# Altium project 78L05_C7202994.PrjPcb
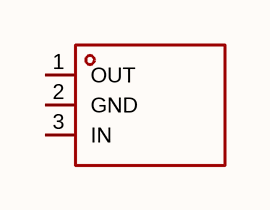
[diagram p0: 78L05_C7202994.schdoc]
1 sheet, 1 parts. Net scope: global (net labels, ports and power ports of the same name join across sheets).

## Sheet 78L05_C7202994.schdoc
size 127 x 101 mm

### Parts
U?  78l05_c7202994  [SOT-89-3_L4.5-W2.5-P1.50-LS4.2-BR]  (value not drawn)

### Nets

Not connected (* = marked no-connect by the designer): U? 1(OUT) 2(GND) 3(IN)

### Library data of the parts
U? = 78l05_c7202994: 输出极性:正极;工作电压:30V;输出电压:5V;输出电流:100mA;电源纹波抑制比(PSRR):49dB@(120Hz);输出类型:固定;; Manufacturer: TECH PUBLIC(台舟); ManufacturerPart: 78L05; AddInBom: yes; ModelId: 6db690b7897d4d18a30d90c1b89525ee; ModelName: SOT-89-3_L4.3-W2.5-H1.6-LS4.1-P1.50; ModelTransform: 161.417,169.291,0,180,0,0,-18.661,0,0; Output Configuration: 正极; Voltage - Supply: 30V; Output Voltage: 5V; Output Current: 100mA; Voltage Dropout: 1.7V; standby current: 3.8mA; Noise: 42uVrms; Output Type: 固定; Number of Outputs: 1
